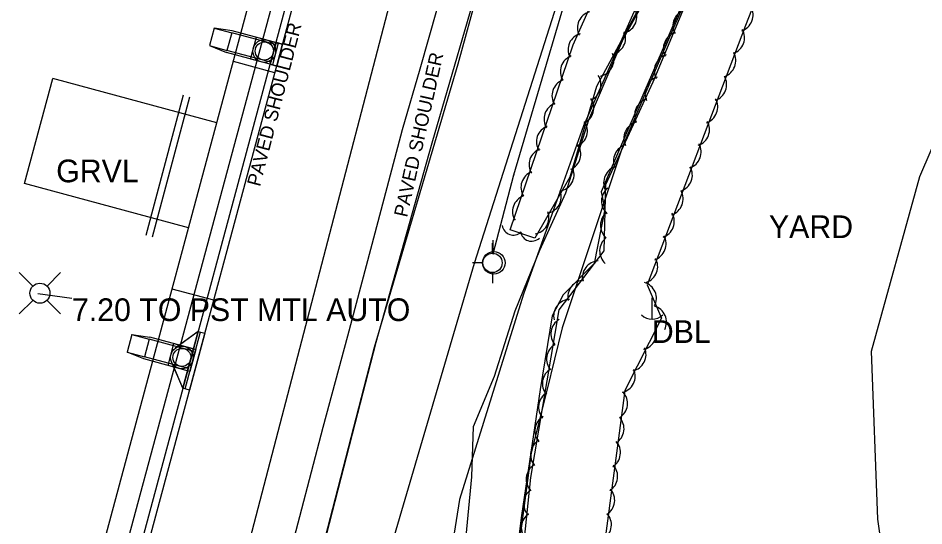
# Model space of a CAD drawing. Extents: x 978516 to 993312, y 1836504 to 1846212.
# Drawn here: x 992546.6 to 992746.5, y 1840163.6 to 1840275.6 of the extents above; entities that cross this region are included whole.
import ezdxf

# ---------------------------------------------------------------- set-up
doc = ezdxf.new("R2010")
doc.units = 0
for name, color, linetype in [('R_Drainage', 7, 'Continuous'), ('R_Proposed Road', 7, 'Continuous'), ('R_SideDrains', 7, 'Continuous'), ('S_BASELINE', 7, 'Continuous'), ('S_EDGE_PAVEMENT', 7, 'Continuous'), ('S_FIBER_OPTIC_CABLE', 7, 'Continuous'), ('S_GAS_UTILITIES', 7, 'Continuous'), ('S_PARKING', 7, 'Continuous'), ('S_SHOULDER', 7, 'Continuous'), ('S_SHOULDER_ANNOT', 7, 'Continuous'), ('S_SIGN', 7, 'Continuous'), ('S_SIGN_ANNOT', 7, 'Continuous'), ('S_STREAM', 7, 'Continuous'), ('S_SURVEY_TEXT_ANNOT', 7, 'Continuous'), ('S_TREE', 7, 'Continuous'), ('S_UTILITY_POLE', 7, 'Continuous'), ('S_UTILITY_POLE_ANNOT', 7, 'Continuous'), ('S_UTL_PT_SYM', 7, 'Continuous')]:
    doc.layers.add(name, color=color, linetype=linetype)

msp = doc.modelspace()

# ---------------------------------------------------------------- linework, layer by layer
at = {"layer": 'R_Drainage'}
for p, q in [((992589.88, 1840273.41), (992588.84, 1840269.55)), ((992593.87, 1840272.85), (992589.88, 1840273.41)), ((992589.88, 1840273.41), (992593.74, 1840272.37)), ((992593.74, 1840272.37), (992592.7, 1840268.51)), ((992603.4, 1840269.77), (992593.74, 1840272.37)), ((992604.01, 1840270.13), (992593.87, 1840272.85)), ((992588.84, 1840269.55), (992592.57, 1840268.03)), ((992588.84, 1840269.55), (992592.7, 1840268.51)), ((992597.88, 1840266.6), (992599.18, 1840271.43)), ((992603.4, 1840269.77), (992602.36, 1840265.91)), ((992604.01, 1840270.13), (992602.71, 1840265.3)), ((992602.71, 1840265.3), (992592.57, 1840268.03)), ((992602.36, 1840265.91), (992592.7, 1840268.51)), ((992602.23, 1840265.43), (992603.67, 1840265.04)), ((992571.68, 1840205.82), (992570.64, 1840201.96)), ((992571.68, 1840205.82), (992575.54, 1840204.78)), ((992571.68, 1840205.82), (992575.68, 1840205.27)), ((992586.37, 1840206.52), (992581.27, 1840202.78)), ((992586.37, 1840206.52), (992582.24, 1840203.5)), ((992583.47, 1840193.84), (992586.85, 1840206.39)), ((992583.47, 1840193.84), (992586.85, 1840206.39)), ((992575.54, 1840204.78), (992574.5, 1840200.92)), ((992585.2, 1840202.18), (992575.54, 1840204.78)), ((992585.81, 1840202.53), (992575.68, 1840205.27)), ((992579.69, 1840199), (992580.99, 1840203.83)), ((992574.38, 1840200.44), (992570.64, 1840201.96)), ((992570.64, 1840201.96), (992574.5, 1840200.92)), ((992585.2, 1840202.18), (992584.16, 1840198.32)), ((992584.51, 1840197.7), (992574.38, 1840200.44)), ((992584.16, 1840198.32), (992574.5, 1840200.92)), ((992582.99, 1840193.97), (992580.46, 1840199.77)), ((992582.99, 1840193.97), (992580.94, 1840198.67))]:
    msp.add_line(p, q, dxfattribs=at)
for points in [[(992597.88, 1840266.6), (992599.18, 1840271.43), (992604.01, 1840270.13), (992602.71, 1840265.3)], [(992602.23, 1840265.43), (992603.52, 1840270.26), (992604.97, 1840269.87), (992603.67, 1840265.04)], [(992582.99, 1840193.97), (992586.37, 1840206.52), (992587.82, 1840206.13), (992584.44, 1840193.58)], [(992582.99, 1840193.97), (992586.37, 1840206.52), (992587.82, 1840206.13), (992584.44, 1840193.58)], [(992579.69, 1840199), (992580.99, 1840203.83), (992585.81, 1840202.53), (992584.51, 1840197.7)]]:
    msp.add_lwpolyline(points, close=True, dxfattribs=at)
msp.add_lwpolyline([(992603.67, 1840265.04), (992604.97, 1840269.87), (992603.52, 1840270.26), (992602.23, 1840265.43)], dxfattribs=at)
for centre, radius in [((992600.94, 1840268.36), 2.5), ((992600.94, 1840268.36), 2.5), ((992600.94, 1840268.36), 2), ((992600.94, 1840268.36), 2), ((992582.75, 1840200.77), 2.5), ((992582.75, 1840200.77), 2.5), ((992582.75, 1840200.77), 2.5), ((992582.75, 1840200.77), 2.5), ((992582.75, 1840200.77), 2), ((992582.75, 1840200.77), 2), ((992582.75, 1840200.77), 2), ((992582.75, 1840200.77), 2)]:
    msp.add_circle(centre, radius, dxfattribs=at)
at = {"layer": 'R_Proposed Road'}
for p, q in [((992535.45, 1840048.13), (992600.58, 1840290.11)), ((992540.28, 1840046.84), (992605.41, 1840288.81)), ((992543.18, 1840046.06), (992608.31, 1840288.03)), ((992544.63, 1840045.67), (992609.76, 1840287.64)), ((992603.28, 1840263.59), (992594.11, 1840266.06)), ((992548.02, 1840239.11), (992554.26, 1840262.29)), ((992590.47, 1840252.54), (992554.26, 1840262.29)), ((992584.23, 1840229.37), (992548.02, 1840239.11)), ((992589.77, 1840213.38), (992580.59, 1840215.85))]:
    msp.add_line(p, q, dxfattribs=at)
at = {"layer": 'R_SideDrains'}
for p, q in [((992574.84, 1840227.75), (992583.07, 1840258.67)), ((992576.29, 1840227.36), (992584.52, 1840258.29))]:
    msp.add_line(p, q, dxfattribs=at)
at = {"layer": 'S_BASELINE'}
msp.add_line((992692.91, 1840525.06), (992469.46, 1839669.75), dxfattribs=at)
at = {"layer": 'S_EDGE_PAVEMENT'}
msp.add_lwpolyline([(992679.83, 1840395.82), (992671.68, 1840374.91), (992663.53, 1840354), (992659.36, 1840341.66), (992655.2, 1840329.32), (992651.03, 1840316.98), (992646.87, 1840304.65), (992642.99, 1840291.22), (992639.11, 1840277.8), (992635.23, 1840264.38), (992631.35, 1840250.96), (992625.34, 1840228.22), (992619.33, 1840205.49), (992613.83, 1840185.31), (992608.69, 1840165.63), (992603.54, 1840145.94)], dxfattribs=at)
at = {"layer": 'S_FIBER_OPTIC_CABLE'}
for p, q in [((992655.97, 1840241.05), (992671.72, 1840294.34)), ((992651.44, 1840223.65), (992655.97, 1840241.05))]:
    msp.add_line(p, q, dxfattribs=at)
at = {"layer": 'S_GAS_UTILITIES'}
for p, q in [((992647.35, 1840221.55), (992670.09, 1840293.07)), ((992624.87, 1840145.24), (992647.35, 1840221.55))]:
    msp.add_line(p, q, dxfattribs=at)
at = {"layer": 'S_PARKING'}
msp.add_lwpolyline([(992758.32, 1840120.5), (992753.69, 1840120.82), (992739.14, 1840121.77), (992739.62, 1840142.03), (992736.36, 1840165.11), (992734.9, 1840202.15), (992745.57, 1840240.66), (992756.26, 1840265.48), (992768.16, 1840297.32), (992783.66, 1840334.94), (992800.24, 1840378.79), (992826.11, 1840433.86), (992833.55, 1840438.81), (992821.24, 1840446.35), (992808.43, 1840467.32)], dxfattribs=at)
at = {"layer": 'S_SHOULDER'}
for points in [[(992717.38, 1840464.52), (992710.22, 1840449.16), (992701.13, 1840426.2), (992689.81, 1840403.05), (992677.84, 1840371.95), (992667.61, 1840339.8), (992652.64, 1840298.18), (992643.63, 1840265.47), (992625.17, 1840202.99), (992614.29, 1840160.82), (992602.66, 1840116.12)], [(992685.83, 1840393.66), (992678.72, 1840373.27), (992671.62, 1840352.88), (992667.09, 1840340.08), (992662.56, 1840327.28), (992658.03, 1840314.47), (992653.5, 1840301.67), (992649.6, 1840288.26), (992645.7, 1840274.84), (992641.8, 1840261.43), (992637.9, 1840248.01), (992631.73, 1840226.03), (992625.57, 1840204.04), (992620.29, 1840183.81), (992615.28, 1840164.1), (992610.27, 1840144.39)]]:
    msp.add_lwpolyline(points, dxfattribs=at)
at = {"layer": 'S_SIGN'}
msp.add_line((992558.48, 1840213.8), (992550.96, 1840214.83), dxfattribs=at)
at = {"layer": 'S_STREAM'}
for points in [[(992751.9, 1840465.14), (992753.76, 1840440.65), (992746.42, 1840422.99), (992744.79, 1840411.76), (992735.52, 1840394.42), (992729.41, 1840381.19), (992730.5, 1840375.02), (992722.65, 1840349.89), (992713.89, 1840327.1), (992701.8, 1840298.75), (992680.46, 1840249.31), (992675.27, 1840237.31), (992676.06, 1840233.45), (992673.73, 1840221.5), (992666.9, 1840214.58), (992664.48, 1840209.97), (992661.8, 1840193.68), (992657.68, 1840165.91), (992654.52, 1840140.98), (992654.44, 1840125.57), (992654.52, 1840111.92)], [(992725.57, 1840391.67), (992717.91, 1840378.21), (992711.11, 1840356.31), (992704.32, 1840334.41), (992697.18, 1840314.21), (992690.03, 1840294.01), (992680.71, 1840272.95), (992671.39, 1840251.89), (992664.78, 1840233.31), (992658.16, 1840214.73), (992651.08, 1840192.08), (992644, 1840169.43), (992641.83, 1840155.55), (992639.66, 1840141.68), (992640.62, 1840127), (992641.57, 1840112.33), (992638.13, 1840091.46), (992634.62, 1840078.6), (992631.11, 1840065.73), (992627.6, 1840052.87), (992624.09, 1840040), (992617.13, 1840016.71), (992613.83, 1840000.44)], [(992735.04, 1840383.73), (992728.7, 1840365.18), (992721.75, 1840347.39), (992714.8, 1840329.6), (992708.94, 1840315.24), (992703.08, 1840300.88), (992697.32, 1840287.52), (992691.56, 1840274.16), (992685.8, 1840260.8), (992680.04, 1840247.44), (992673.37, 1840227.36), (992666.7, 1840207.27), (992663.27, 1840193.5), (992659.84, 1840179.72), (992657.36, 1840160.87), (992654.88, 1840142.02), (992654.72, 1840125.4), (992654.55, 1840108.77), (992650.29, 1840087.59), (992647.15, 1840075.45), (992644.01, 1840063.3), (992640.87, 1840051.16), (992637.73, 1840039.02), (992635.55, 1840015.63)], [(992640.53, 1840116.8), (992640.72, 1840136.05), (992645.14, 1840157.54), (992646.75, 1840174.41), (992647.12, 1840185.53), (992651.75, 1840196.62), (992656.31, 1840211.05), (992661.71, 1840224.45), (992667.47, 1840237.08), (992672.54, 1840253.16), (992680.2, 1840271.12), (992690.49, 1840289.69), (992695.14, 1840301.65), (992698.7, 1840316.25), (992704.16, 1840328.59), (992710.94, 1840347.07), (992715.14, 1840362.74), (992719.66, 1840380.19)]]:
    msp.add_lwpolyline(points, dxfattribs=at)
at = {"layer": 'S_TREE'}
for points in [[(992741.05, 1840463.84), (992745.98, 1840453.87), (992745.62, 1840441.63), (992736.16, 1840412.83), (992717.26, 1840370.96), (992704.39, 1840328.82), (992691.36, 1840292.3), (992674.25, 1840260.52), (992668.39, 1840240.56), (992660.65, 1840227.05), (992655.21, 1840228.91), (992669.09, 1840269.72), (992682.27, 1840299.38), (992691.67, 1840331.36), (992703.25, 1840366.22), (992719.16, 1840406.11), (992727.68, 1840433.94), (992731.06, 1840446.88), (992731.43, 1840457.73), (992731.62, 1840463.28)], [(992758.49, 1840417.97), (992731.36, 1840335.88), (992707.13, 1840273.99), (992685.4, 1840216.79), (992688.6, 1840209.4), (992680.5, 1840193.49), (992673.67, 1840142.04), (992674.46, 1840118.38), (992668.99, 1840109.14), (992655.98, 1840110.28), (992655.02, 1840129.02), (992659.76, 1840174.32), (992666.01, 1840211.3), (992675.93, 1840224.27), (992676.34, 1840238.95), (992686.72, 1840261.56), (992702.62, 1840299.65), (992717.89, 1840336.94), (992731.19, 1840373.91), (992729.78, 1840378.57), (992733.73, 1840388.79)]]:
    msp.add_lwpolyline(points, dxfattribs=at)
for centre, major_axis, ratio, start_param, end_param in [((992705.22, 1840276.29), (1.17, 3.45), 0.98172, 3.778943, 5.552143), ((992673.69, 1840273.51), (-2.15, -2.94), 0.999853, 4.038445, 5.811645), ((992679.51, 1840275.91), (1.73, 3.21), 0.999867, 3.825789, 5.598989), ((992694.7, 1840273.98), (-1.53, -3.31), 0.981811, 3.864398, 5.637599), ((992671.61, 1840268.66), (-2.15, -2.94), 0.999853, 4.038445, 5.811645), ((992677.03, 1840271.22), (1.73, 3.21), 0.999867, 3.825789, 5.598989), ((992692.6, 1840268.96), (-1.53, -3.31), 0.981811, 3.864398, 5.637599), ((992703.35, 1840271.3), (1.07, 3.48), 0.981644, 3.759144, 5.532345), ((992674.44, 1840266.43), (1.73, 3.21), 0.999867, 3.825789, 5.598989), ((992701.41, 1840266.21), (1.07, 3.48), 0.981644, 3.759144, 5.532345), ((992669.91, 1840263.86), (-1.17, -3.45), 0.999852, 3.825789, 5.598989), ((992690.59, 1840264.05), (-1.53, -3.31), 0.981811, 3.864398, 5.637599), ((992668.06, 1840258.52), (-1.17, -3.45), 0.999852, 3.825789, 5.598989), ((992671.59, 1840260.93), (1.03, 3.5), 0.999849, 3.825789, 5.598989), ((992688.53, 1840259.08), (-1.52, -3.31), 0.982019, 3.825789, 5.598989), ((992699.38, 1840260.95), (1.07, 3.48), 0.981644, 3.759144, 5.532345), ((992670.02, 1840255.84), (1.03, 3.5), 0.999849, 3.825789, 5.598989), ((992686.24, 1840254.26), (-1.52, -3.31), 0.982019, 3.825789, 5.598989), ((992697.42, 1840255.98), (1.07, 3.48), 0.981644, 3.759144, 5.532345), ((992666.31, 1840253.37), (-1.17, -3.45), 0.999852, 3.825789, 5.598989), ((992664.63, 1840248.34), (-1.17, -3.45), 0.999852, 3.825789, 5.598989), ((992668.6, 1840250.75), (1.03, 3.5), 0.999849, 3.825789, 5.598989), ((992683.86, 1840249.14), (-1.52, -3.31), 0.982019, 3.825789, 5.598989), ((992695.61, 1840251.02), (1.07, 3.48), 0.981644, 3.759144, 5.532345), ((992667.14, 1840245.65), (1.03, 3.5), 0.999849, 3.825789, 5.598989), ((992681.59, 1840244.19), (-1.52, -3.31), 0.982019, 3.825789, 5.598989), ((992693.76, 1840246.05), (1.07, 3.48), 0.981644, 3.759144, 5.532345), ((992663, 1840243.32), (-1.17, -3.45), 0.999852, 3.825789, 5.598989), ((992661.21, 1840238.29), (-1.17, -3.45), 0.999852, 3.825789, 5.598989), ((992665.65, 1840241.08), (1.81, 3.16), 0.99987, 3.825789, 5.598989), ((992679.41, 1840239.36), (-1.52, -3.31), 0.982019, 3.825789, 5.598989), ((992691.82, 1840240.96), (1.07, 3.48), 0.981644, 3.759144, 5.532345), ((992678.93, 1840235.25), (-0.43, -3.62), 0.982476, 3.917983, 5.691184), ((992659.36, 1840232.95), (-1.17, -3.45), 0.999852, 3.825789, 5.598989), ((992662.82, 1840236.19), (1.81, 3.16), 0.99987, 3.825789, 5.598989), ((992689.79, 1840235.7), (1.07, 3.48), 0.981644, 3.759144, 5.532345), ((992660.1, 1840231.6), (1.81, 3.16), 0.99987, 3.825789, 5.598989), ((992678.71, 1840229.92), (-0.43, -3.62), 0.982476, 3.917983, 5.691184), ((992687.83, 1840230.74), (1.07, 3.48), 0.981644, 3.759144, 5.532345), ((992656.28, 1840231.32), (1.21, 3.44), 0.7987, 2.261888, 4.035089), ((992660.3, 1840229.98), (1.21, 3.44), 0.7987, 2.261888, 4.035089), ((992686.02, 1840225.77), (1.07, 3.48), 0.981644, 3.759144, 5.532345), ((992678.52, 1840224.28), (-0.43, -3.62), 0.982476, 3.917983, 5.691184), ((992674.72, 1840218.43), (-2.21, -2.89), 0.984076, 3.825789, 5.598989), ((992684.17, 1840220.8), (1.07, 3.48), 0.981644, 3.759144, 5.532345), ((992671.53, 1840214.2), (-2.21, -2.89), 0.984076, 3.825789, 5.598989), ((992683.86, 1840213.8), (-1.45, 3.34), 0.988709, 3.825789, 5.598989), ((992668.38, 1840209.96), (-2.21, -2.89), 0.984076, 3.825789, 5.598989), ((992686.08, 1840208.6), (-1.45, 3.34), 0.988709, 3.825789, 5.598989), ((992667.76, 1840205.96), (-0.27, -3.63), 0.981568, 3.729538, 5.502738), ((992683.91, 1840206.11), (1.65, 3.25), 0.982278, 3.825789, 5.598989), ((992666.79, 1840200.4), (-0.27, -3.63), 0.981568, 3.729538, 5.502738), ((992681.58, 1840201.37), (1.65, 3.25), 0.982278, 3.825789, 5.598989), ((992665.87, 1840195.04), (-0.27, -3.63), 0.981568, 3.729538, 5.502738), ((992679.2, 1840196.62), (1.65, 3.25), 0.982278, 3.825789, 5.598989), ((992665.03, 1840189.8), (-0.27, -3.63), 0.981568, 3.729538, 5.502738), ((992677.51, 1840190.62), (0.48, 3.61), 0.981906, 3.825789, 5.598989), ((992664.21, 1840184.58), (-0.27, -3.63), 0.981568, 3.729538, 5.502738), ((992676.74, 1840185.02), (0.48, 3.61), 0.981906, 3.825789, 5.598989), ((992663.25, 1840179.34), (-0.27, -3.63), 0.981568, 3.729538, 5.502738), ((992675.96, 1840179.75), (0.48, 3.61), 0.981906, 3.825789, 5.598989), ((992662.31, 1840173.94), (-0.22, -3.64), 0.982011, 3.78181, 5.555011), ((992675.34, 1840174.5), (0.48, 3.61), 0.981906, 3.825789, 5.598989), ((992674.68, 1840169.24), (0.48, 3.61), 0.981906, 3.825789, 5.598989), ((992661.74, 1840168.53), (-0.22, -3.64), 0.982011, 3.78181, 5.555011), ((992661.23, 1840163.25), (-0.22, -3.64), 0.982011, 3.78181, 5.555011), ((992673.96, 1840163.84), (0.48, 3.61), 0.981906, 3.825789, 5.598989)]:
    msp.add_ellipse(centre, major_axis=major_axis, ratio=ratio, start_param=start_param, end_param=end_param, dxfattribs=at)
at = {"layer": 'S_UTILITY_POLE'}
for p, q in [((992651.3, 1840223.74), (992651.3, 1840225.99)), ((992651.45, 1840224.15), (992651.45, 1840226.63)), ((992649.21, 1840221.61), (992646.88, 1840221.61)), ((992549.82, 1840216.52), (992546.84, 1840219.51)), ((992553, 1840216.52), (992555.99, 1840219.51)), ((992651.38, 1840217.19), (992651.38, 1840219.52)), ((992686.44, 1840213.91), (992686.44, 1840209.18)), ((992549.82, 1840213.35), (992546.84, 1840210.36)), ((992553, 1840213.35), (992555.99, 1840210.36))]:
    msp.add_line(p, q, dxfattribs=at)
for centre, radius in [((992651.59, 1840221.63), 2.5), ((992651.3, 1840221.63), 2.13), ((992551.42, 1840214.94), 2.21)]:
    msp.add_circle(centre, radius, dxfattribs=at)
msp.add_arc((992686.5, 1840212.61), 3.41, 226.3972, 313.6028, dxfattribs=at)
at = {"layer": 'S_UTL_PT_SYM'}
for points in [[(992655.97, 1840241.05), (992655.97, 1840241.1), (992655.97, 1840241.05), (992655.92, 1840241.05), (992655.97, 1840241.05), (992655.97, 1840241), (992655.97, 1840241.05), (992656.02, 1840241.05)], [(992651.44, 1840223.65), (992651.44, 1840223.7), (992651.44, 1840223.65), (992651.39, 1840223.65), (992651.44, 1840223.65), (992651.44, 1840223.6), (992651.44, 1840223.65), (992651.49, 1840223.65)], [(992647.35, 1840221.55), (992647.35, 1840221.6), (992647.35, 1840221.55), (992647.3, 1840221.55), (992647.35, 1840221.55), (992647.35, 1840221.5), (992647.35, 1840221.55), (992647.4, 1840221.55)]]:
    msp.add_lwpolyline(points, dxfattribs=at)

# ---------------------------------------------------------------- texts
at = {"layer": 'S_SHOULDER_ANNOT'}
for rotation, p in [(75.5837, (992599.98, 1840238.32)), (77.4395, (992632.44, 1840231.55))]:
    msp.add_text('PAVED SHOULDER', height=3.0003, rotation=rotation, dxfattribs=at).set_placement(p)
at = {"layer": 'S_SIGN_ANNOT'}
msp.add_text('7.20 TO PST MTL AUTO', height=5, dxfattribs=at).set_placement((992558.48, 1840208.8))
at = {"layer": 'S_SURVEY_TEXT_ANNOT'}
for s, p in [('GRVL', (992555.01, 1840239.41)), ('YARD', (992712.3, 1840227.11))]:
    msp.add_text(s, height=5, dxfattribs=at).set_placement(p)
at = {"layer": 'S_UTILITY_POLE_ANNOT'}
msp.add_text('DBL', height=5, dxfattribs=at).set_placement((992686.45, 1840203.97))

doc.saveas('drawing.dxf')
